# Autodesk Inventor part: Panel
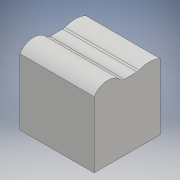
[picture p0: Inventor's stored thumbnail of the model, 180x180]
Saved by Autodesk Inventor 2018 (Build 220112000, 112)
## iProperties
Created: 2022-01
Part Number: Panel
Material: Generic
Document SubType Name: Modeling
Designer: Asus
Density: 1 g/cm^3
Appearance: Default
Author: Asus
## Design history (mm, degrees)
sketch "Boceto1"
  geometry: L1 (135, 120)-(-135, 120); L2 (-135, 120)-(-135, -120); L3 (-135, -120)-(135, -120); L4 (135, -120)-(135, 120); L5 (135, 120)-(-135, -120); L6 (-135, 120)-(135, -120); 1 further point
  constraints: 12 end point, 2 midpoint, 2 parallel, 1 horizontal, 1 perpendicular
  dimensions: "d0" = 270 distance of L3.end L2.end; "d1" = 240 distance of L2.end L1.end
extrude "Extrusión1" new body sketch "Boceto1" distance "d2" = 240; taper "d3" = 0 deg
sketch "Boceto2"
  geometry: L1 (0, 0)-(0, 240) reference; L2 (0, 240)-(0, 160); L3 (0, 100)-(0, 0); A1 r 60 centre (33.166, 50) between (0, 100) and (0, 0); A2 r 93.389 centre (84.389, 200) between (0, 240) and (0, 160); 1 further point
  constraints: 5 point on circle, 4 end point, 2 centre point, 1 collinear, 1 point on line
  dimensions: "d4" = 100 distance of A1.end L3.start; "d5" = 60 radius of A1; "d6" = 80 distance of L1.end L2.end
extrude "Extrusión2" join sketch "Boceto2" distance "d7" = 270; taper "d8" = 0 deg
fillet "Empalme1" dims "d9" = 20
node "Sólido1"
